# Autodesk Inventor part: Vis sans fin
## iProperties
Shininess: 64.0
Length Units: 11269
Angle Units: 11279
Time Units: 11290
Mass Units: 11283
Length Display Precision: 3
Angle Display Precision: 2
Compacted: True
Part Number: Vis sans fin
Document SubType Name: Modeling
Created: 2003-05
Material: Par défaut
Designer: Philippe
Density: 0.0
Volumn: 0.0
Area: 0.0
PropertySet Name: Model Information
Control State: 0
Master: False
Checked Out: False
Author: Philippe
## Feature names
1. Révolution1 [Revolution]
2. Extrusion1
3. Chanfrein1 [Chamfer]
4. Hélicoïde2
5. Réseau circulaire1 [Circular Pattern]
6. Révolution2 [Revolution]
